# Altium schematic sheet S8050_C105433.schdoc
size 127 x 101 mm
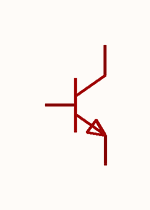
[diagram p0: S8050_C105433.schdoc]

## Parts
Q?  s8050(range:120-200)  [SOT-23-3_L2.9-W1.6-P1.90-LS2.8-BR]  (value not drawn)

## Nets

Not connected (* = marked no-connect by the designer): Q? 1 2 3

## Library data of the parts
Q? = s8050(range:120-200): 晶体管类型:NPN;集电极电流(Ic):500mA;集射极击穿电压(Vceo):25V;耗散功率(Pd):300mW;直流电流增益(hFE):120;; Manufacturer: CJ(江苏长电/长晶); Symbol: S8050_C105433; AddInBom: yes; ModelId: 89cb27a44ab2466697082bb9fd73a7d0; ModelName: SOT-23-3L_L2.9-W1.6-H1.1-LS2.8-P0.95; ModelTransform: 114.173,110.236,0,90,0,0,0,0,0; type: NPN; Current - Collector(Ic): 500mA; Collector - Emitter Voltage VCEO: 25V; Pd - Power Dissipation: 300mW; DC Current Gain: 120; Transition frequency(fT): 150MHz; Current - Collector Cutoff: 100nA; Vce Saturation(VCE(sat)): 600mV; Emitter-Base Voltage(Vebo): 5V; Number: 1个NPN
